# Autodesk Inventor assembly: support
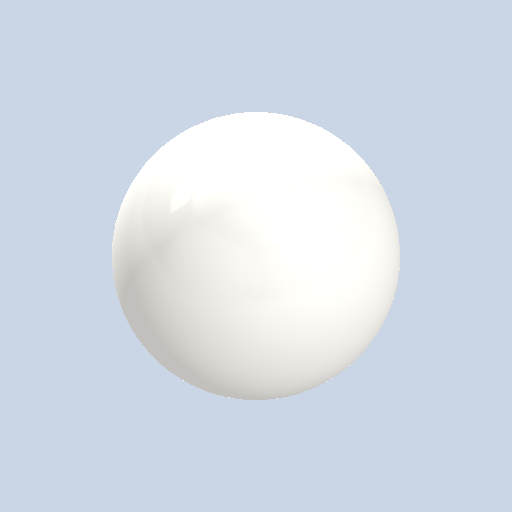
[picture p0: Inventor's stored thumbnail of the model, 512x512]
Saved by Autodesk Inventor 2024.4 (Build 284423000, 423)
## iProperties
Created: 2025-07
Part Number: support
Document SubType Name: Assembly
Designer: AdminForWorker
Title: support v1
Author: AdminForWorker
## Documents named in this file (2)
- c:\worker\convert-fusion-r03-cosv3\tmp\job-1\5\temp\files\c2717cec-cd30-4e2b-a2e5-52afbc4802da\support v1_1.iam
- c:\worker\convert-fusion-r03-cosv3\tmp\job-1\5\temp\files\c2717cec-cd30-4e2b-a2e5-52afbc4802da\Component1.ipt
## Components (1 placed, 1 different names)
1. Component1:1
